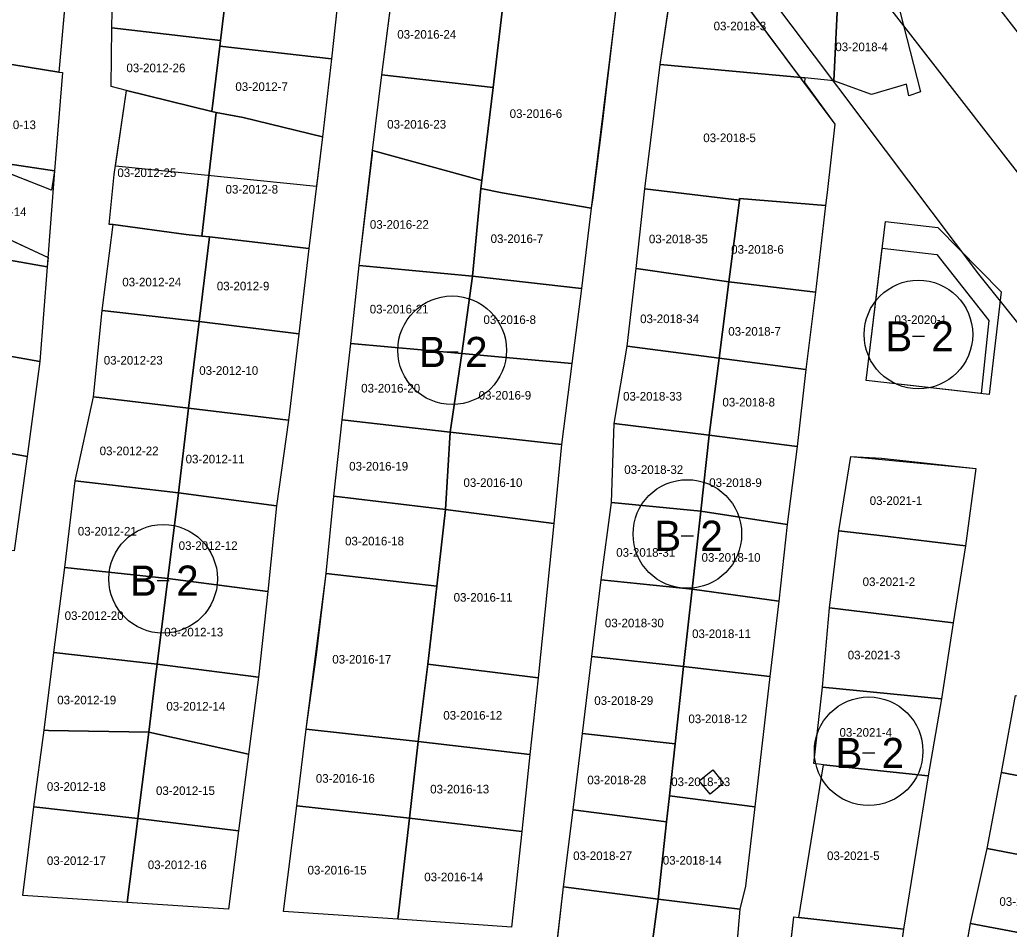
# Model space of a CAD drawing. Extents: x 413946 to 415528, y 4453939 to 4454944.
# Drawn here: x 414419.7 to 414534.5, y 4454655 to 4454760.5 of the extents above; entities that cross this region are included whole.
import ezdxf

# ---------------------------------------------------------------- set-up
doc = ezdxf.new("R2010")
doc.units = 0
for name, color, linetype in [('0_KADASTRO', 7, 'Continuous'), ('Level 27', 7, 'Continuous'), ('Level 29', 7, 'Continuous'), ('Level 54', 7, 'Continuous'), ('Level 62', 7, 'Continuous'), ('SEMBOL', 7, 'Continuous')]:
    doc.layers.add(name, color=color, linetype=linetype)

msp = doc.modelspace()

# ---------------------------------------------------------------- linework, layer by layer
at = {"layer": '0_KADASTRO'}
for points in [[(414411.09, 4454757.71), (414412.42, 4454768.39), (414424.89, 4454766.54), (414425.29, 4454766.49), (414424.24, 4454754.37), (414417.32, 4454755.48), (414417.48, 4454756.27), (414416.84, 4454756.42)], [(414430.38, 4454759.52), (414430.4, 4454761.44), (414431.26, 4454768.85), (414442.27, 4454767.59), (414443.18, 4454767.49), (414444.11, 4454767.4), (414442.98, 4454758.06)], [(414442.9, 4454757.4), (414442.98, 4454758.06), (414444.11, 4454767.4), (414456.96, 4454765.91), (414455.86, 4454755.93)], [(414461.7, 4454754.08), (414463.1, 4454764.94), (414475.92, 4454763.42), (414474.61, 4454752.59)], [(414494.02, 4454755.26), (414495.53, 4454765.54), (414514.68, 4454763.78), (414514.15, 4454753.38), (414510.8, 4454753.7)], [(414514.15, 4454753.38), (414514.68, 4454763.78), (414522.82, 4454763.48), (414523.07, 4454763.47), (414521.83, 4454761.44), (414524.23, 4454752.08), (414522.87, 4454751.64), (414522.59, 4454752.99), (414518.54, 4454751.77)], [(414473.21, 4454740.87), (414473.3, 4454741.81), (414474.61, 4454752.59), (414475.92, 4454763.42), (414488.85, 4454761.81), (414487.71, 4454752), (414487.32, 4454748.7), (414486.14, 4454739.52), (414486, 4454738.59), (414475.68, 4454740.39)], [(414430.3, 4454752.72), (414430.38, 4454759.52), (414442.98, 4454758.06), (414442.9, 4454757.4), (414441.97, 4454749.8), (414432.06, 4454752.24)], [(414441.97, 4454749.8), (414442.9, 4454757.4), (414455.86, 4454755.93), (414454.84, 4454746.86), (414445.62, 4454749.13), (414442.5, 4454749.69)], [(414414.39, 4454744.32), (414414.9, 4454747.24), (414416.84, 4454756.42), (414417.48, 4454756.27), (414417.32, 4454755.48), (414424.24, 4454754.37), (414424.66, 4454754.32), (414423.72, 4454742.92)], [(414492.24, 4454740.85), (414494.02, 4454755.26), (414510.8, 4454753.7), (414510.77, 4454753.18), (414514.29, 4454748.36), (414513.38, 4454740.43), (414513.21, 4454738.92), (414503.23, 4454739.74), (414503.2, 4454739.52)], [(414460.64, 4454745.28), (414461.7, 4454754.08), (414474.61, 4454752.59), (414473.3, 4454741.81)], [(414430.05, 4454736.72), (414430.65, 4454742.52), (414432.06, 4454752.24), (414441.97, 4454749.8), (414442.5, 4454749.69), (414440.81, 4454735.35), (414439.01, 4454735.53), (414430.52, 4454736.69)], [(414440.81, 4454735.35), (414442.5, 4454749.69), (414445.62, 4454749.13), (414454.84, 4454746.86), (414453.25, 4454733.91), (414441.72, 4454735.26)], [(414412.99, 4454733.55), (414413.48, 4454737.28), (414414.39, 4454744.32), (414423.72, 4454742.92), (414422.89, 4454731.8)], [(414459.08, 4454731.97), (414459.3, 4454733.89), (414460.63, 4454744.86), (414460.64, 4454745.28), (414473.3, 4454741.81), (414473.21, 4454740.87), (414472.22, 4454730.73)], [(414472.22, 4454730.73), (414473.21, 4454740.87), (414475.68, 4454740.39), (414486, 4454738.59), (414484.86, 4454729.29)], [(414491.24, 4454731.59), (414492.24, 4454740.85), (414503.2, 4454739.52), (414501.98, 4454730.07)], [(414501.98, 4454730.07), (414503.2, 4454739.52), (414503.23, 4454739.74), (414513.21, 4454738.92), (414512.05, 4454728.87)], [(414429.27, 4454726.72), (414430.52, 4454736.69), (414439.01, 4454735.53), (414440.81, 4454735.35), (414441.72, 4454735.26), (414440.51, 4454725.47)], [(414517.93, 4454718.61), (414520.15, 4454737.04), (414526.21, 4454736.36), (414533.56, 4454728.9), (414532.17, 4454717)], [(414440.51, 4454725.47), (414441.72, 4454735.26), (414453.25, 4454733.91), (414452.09, 4454724.02)], [(414411.31, 4454722.72), (414412.02, 4454727.29), (414412.99, 4454733.55), (414422.89, 4454731.8), (414422.02, 4454720.81)], [(414458.1, 4454722.9), (414459.08, 4454731.97), (414472.22, 4454730.73), (414470.99, 4454721.74)], [(414490.16, 4454722.6), (414491.24, 4454731.59), (414501.98, 4454730.07), (414500.84, 4454721.21)], [(414470.99, 4454721.74), (414472.22, 4454730.73), (414484.86, 4454729.29), (414483.76, 4454720.58)], [(414500.84, 4454721.21), (414501.98, 4454730.07), (414512.05, 4454728.87), (414510.91, 4454719.88)], [(414428.26, 4454716.73), (414429.27, 4454726.72), (414440.51, 4454725.47), (414439.26, 4454715.41)], [(414439.26, 4454715.41), (414440.51, 4454725.47), (414452.09, 4454724.02), (414450.88, 4454714.03)], [(414409.93, 4454711.73), (414410.66, 4454717.54), (414411.31, 4454722.72), (414422.02, 4454720.81), (414420.54, 4454709.81)], [(414457.12, 4454714.06), (414458.1, 4454722.9), (414470.99, 4454721.74), (414469.65, 4454712.64)], [(414488.68, 4454713.62), (414490.16, 4454722.6), (414500.84, 4454721.21), (414499.69, 4454712.26)], [(414469.65, 4454712.64), (414470.99, 4454721.74), (414483.76, 4454720.58), (414482.56, 4454711.21)], [(414499.69, 4454712.26), (414500.84, 4454721.21), (414510.91, 4454719.88), (414509.89, 4454710.97)], [(414426.12, 4454706.97), (414428.26, 4454716.73), (414439.26, 4454715.41), (414438.13, 4454705.58)], [(414438.13, 4454705.58), (414439.26, 4454715.41), (414450.88, 4454714.03), (414449.5, 4454704.08)], [(414456.15, 4454705.18), (414457.12, 4454714.06), (414469.65, 4454712.64), (414469.08, 4454703.67)], [(414488.34, 4454704.47), (414488.68, 4454713.62), (414499.69, 4454712.26), (414498.71, 4454703.47)], [(414469.08, 4454703.67), (414469.65, 4454712.64), (414482.56, 4454711.21), (414481.66, 4454702.04)], [(414498.71, 4454703.47), (414499.69, 4454712.26), (414509.89, 4454710.97), (414508.74, 4454701.9)], [(414408.52, 4454700.53), (414409.4, 4454707.53), (414409.93, 4454711.73), (414420.54, 4454709.81), (414419.04, 4454698.87), (414418.26, 4454698.94)], [(414514.73, 4454701.17), (414516.13, 4454709.81), (414519.69, 4454709.59), (414530.63, 4454708.39), (414529.43, 4454699.42), (414519.81, 4454700.58)], [(414424.91, 4454696.94), (414426.12, 4454706.97), (414438.13, 4454705.58), (414436.88, 4454695.64)], [(414436.88, 4454695.64), (414438.13, 4454705.58), (414449.5, 4454704.08), (414448.47, 4454694.14)], [(414455.26, 4454696.22), (414456.15, 4454705.18), (414469.08, 4454703.67), (414468.08, 4454694.75)], [(414487.17, 4454695.5), (414488.34, 4454704.47), (414498.71, 4454703.47), (414497.71, 4454694.41)], [(414467.06, 4454685.72), (414468.08, 4454694.75), (414469.08, 4454703.67), (414481.66, 4454702.04), (414479.83, 4454684.13)], [(414497.71, 4454694.41), (414498.71, 4454703.47), (414508.74, 4454701.9), (414507.78, 4454693.01)], [(414513.64, 4454692.23), (414514.73, 4454701.17), (414519.81, 4454700.58), (414529.43, 4454699.42), (414528, 4454690.52)], [(414423.66, 4454687.08), (414424.91, 4454696.94), (414436.88, 4454695.64), (414435.64, 4454685.73)], [(414452.93, 4454678.19), (414454.13, 4454686.78), (414455.26, 4454696.22), (414468.08, 4454694.75), (414467.06, 4454685.72), (414465.93, 4454676.76)], [(414435.64, 4454685.73), (414436.88, 4454695.64), (414448.47, 4454694.14), (414447.39, 4454684.22)], [(414486.08, 4454686.59), (414487.17, 4454695.5), (414497.71, 4454694.41), (414496.71, 4454685.45)], [(414496.71, 4454685.45), (414497.71, 4454694.41), (414507.78, 4454693.01), (414506.74, 4454684.3)], [(414512.84, 4454683.03), (414513.64, 4454692.23), (414528, 4454690.52), (414526.67, 4454681.7)], [(414422.53, 4454678.05), (414423.66, 4454687.08), (414435.64, 4454685.73), (414435.45, 4454684.28), (414434.65, 4454677.83), (414423.03, 4454678.01)], [(414434.65, 4454677.83), (414435.45, 4454684.28), (414435.64, 4454685.73), (414447.39, 4454684.22), (414446.22, 4454675.29)], [(414465.93, 4454676.76), (414467.06, 4454685.72), (414479.83, 4454684.13), (414478.87, 4454675.25)], [(414484.99, 4454677.67), (414486.08, 4454686.59), (414496.71, 4454685.45), (414495.73, 4454676.48)], [(414495.07, 4454670.43), (414495.73, 4454676.48), (414496.71, 4454685.45), (414506.74, 4454684.3), (414505, 4454669.16)], [(414511.83, 4454674.18), (414512.84, 4454683.03), (414526.67, 4454681.7), (414525.12, 4454672.75), (414512.97, 4454674.05)], [(414533.61, 4454673.15), (414535.24, 4454682.06), (414550.8, 4454679.07), (414549.12, 4454670.2)], [(414421.32, 4454669.17), (414422.53, 4454678.05), (414423.03, 4454678.01), (414434.65, 4454677.83), (414433.39, 4454667.83)], [(414433.39, 4454667.83), (414434.65, 4454677.83), (414446.22, 4454675.29), (414445.07, 4454666.4)], [(414451.84, 4454669.3), (414452.93, 4454678.19), (414465.93, 4454676.76), (414464.93, 4454667.87)], [(414483.9, 4454668.83), (414484.99, 4454677.67), (414495.73, 4454676.48), (414495.07, 4454670.43), (414494.74, 4454667.42)], [(414464.93, 4454667.87), (414465.93, 4454676.76), (414478.87, 4454675.25), (414477.96, 4454666.3)], [(414498.54, 4454672.2), (414500.1, 4454673.47), (414501.34, 4454671.9), (414499.79, 4454670.63)], [(414498.54, 4454672.2), (414500.1, 4454673.47), (414501.34, 4454671.9), (414499.79, 4454670.63)], [(414510.1, 4454656.34), (414512.97, 4454674.05), (414525.12, 4454672.75), (414522.25, 4454654.98)], [(414531.97, 4454664.33), (414533.61, 4454673.15), (414549.12, 4454670.2), (414547.45, 4454661.37)], [(414493.77, 4454658.47), (414494.74, 4454667.42), (414495.07, 4454670.43), (414505, 4454669.16), (414503.89, 4454659.98), (414503.24, 4454657.28)], [(414420.05, 4454658.87), (414421.32, 4454669.17), (414433.39, 4454667.83), (414432.16, 4454658.08)], [(414450.31, 4454657.04), (414451.84, 4454669.3), (414464.93, 4454667.87), (414463.58, 4454656.13)], [(414482.8, 4454659.87), (414483.9, 4454668.83), (414494.74, 4454667.42), (414493.77, 4454658.47)], [(414432.16, 4454658.08), (414433.39, 4454667.83), (414445.07, 4454666.4), (414443.91, 4454657.28)], [(414463.58, 4454656.13), (414464.93, 4454667.87), (414477.96, 4454666.3), (414476.77, 4454655.19)], [(414530.01, 4454655.62), (414531.97, 4454664.33), (414547.45, 4454661.37), (414545.83, 4454652.65)], [(414481.74, 4454650.84), (414482.8, 4454659.87), (414493.77, 4454658.47), (414492.58, 4454649.49)], [(414492.58, 4454649.49), (414493.77, 4454658.47), (414503.24, 4454657.28), (414502.46, 4454648.25)], [(414508.5, 4454647.45), (414509.5, 4454656.41), (414510.1, 4454656.34), (414522.25, 4454654.98), (414520.98, 4454645.92)], [(414528.46, 4454646.74), (414530.01, 4454655.62), (414545.83, 4454652.65), (414544.19, 4454643.58)]]:
    msp.add_lwpolyline(points, close=True, dxfattribs=at)
at = {"layer": 'Level 27'}
for p, q in [((414425.29, 4454766.49), (414424.24, 4454754.37)), ((414456.96, 4454765.91), (414455.86, 4454755.93)), ((414461.7, 4454754.08), (414463.1, 4454764.94)), ((414494.02, 4454755.26), (414495.42, 4454764.81)), ((414430.38, 4454759.52), (414430.4, 4454761.44)), ((414488.85, 4454761.81), (414486, 4454738.59)), ((414430.3, 4454752.72), (414430.38, 4454759.52)), ((414455.86, 4454755.93), (414454.84, 4454746.86)), ((414492.24, 4454740.85), (414494.02, 4454755.26)), ((414424.66, 4454754.32), (414423.72, 4454742.92)), ((414424.24, 4454754.37), (414424.66, 4454754.32)), ((414460.64, 4454745.28), (414461.7, 4454754.08)), ((414432.06, 4454752.24), (414430.3, 4454752.72)), ((414430.79, 4454743.48), (414432.06, 4454752.24)), ((414423.36, 4454740.7), (414404.07, 4454748.25)), ((414454.84, 4454746.86), (414454.13, 4454741.1)), ((414459.08, 4454731.97), (414460.64, 4454745.28)), ((414454.13, 4454741.1), (414430.79, 4454743.48)), ((414423.72, 4454742.92), (414423.36, 4454740.7)), ((414491.24, 4454731.59), (414492.24, 4454740.85)), ((414486, 4454738.59), (414484.86, 4454729.29)), ((414513.21, 4454738.92), (414512.05, 4454728.87)), ((414413.48, 4454737.28), (414422.97, 4454732.88)), ((414429.27, 4454726.72), (414430.52, 4454736.69)), ((414430.52, 4454736.69), (414439.01, 4454735.53)), ((414439.01, 4454735.53), (414440.81, 4454735.35)), ((414440.81, 4454735.35), (414441.72, 4454735.26)), ((414441.72, 4454735.26), (414453.25, 4454733.91)), ((414453.25, 4454733.91), (414452.09, 4454724.02)), ((414517.93, 4454718.61), (414519.78, 4454733.95)), ((414422.97, 4454732.88), (414422.89, 4454731.8)), ((414422.89, 4454731.8), (414422.02, 4454720.81)), ((414458.1, 4454722.9), (414459.08, 4454731.97)), ((414490.16, 4454722.6), (414491.24, 4454731.59)), ((414484.86, 4454729.29), (414483.76, 4454720.58)), ((414512.05, 4454728.87), (414510.91, 4454719.88)), ((414428.26, 4454716.73), (414429.27, 4454726.72)), ((414452.09, 4454724.02), (414450.88, 4454714.03)), ((414457.12, 4454714.06), (414458.1, 4454722.9)), ((414488.68, 4454713.62), (414490.16, 4454722.6)), ((414422.02, 4454720.81), (414420.54, 4454709.81)), ((414483.76, 4454720.58), (414482.56, 4454711.21)), ((414510.91, 4454719.88), (414509.89, 4454710.97)), ((414531.26, 4454717.1), (414517.93, 4454718.61)), ((414426.12, 4454706.97), (414428.26, 4454716.73)), ((414450.88, 4454714.03), (414449.5, 4454704.08)), ((414456.15, 4454705.18), (414457.12, 4454714.06)), ((414488.34, 4454704.47), (414488.68, 4454713.62)), ((414482.56, 4454711.21), (414481.66, 4454702.04)), ((414509.89, 4454710.97), (414508.74, 4454701.9)), ((414420.54, 4454709.81), (414419.04, 4454698.87)), ((414514.73, 4454701.17), (414516.13, 4454709.81)), ((414516.13, 4454709.81), (414530.63, 4454708.39)), ((414530.63, 4454708.39), (414529.43, 4454699.42)), ((414424.91, 4454696.94), (414426.12, 4454706.97)), ((414455.26, 4454696.22), (414456.15, 4454705.18)), ((414449.5, 4454704.08), (414448.47, 4454694.14)), ((414487.17, 4454695.5), (414488.34, 4454704.47)), ((414481.66, 4454702.04), (414479.83, 4454684.13)), ((414508.74, 4454701.9), (414507.78, 4454693.01)), ((414513.64, 4454692.23), (414514.73, 4454701.17)), ((414529.43, 4454699.42), (414528, 4454690.52)), ((414423.66, 4454687.08), (414424.91, 4454696.94)), ((414452.93, 4454678.19), (414455.26, 4454696.22)), ((414486.08, 4454686.59), (414487.17, 4454695.5)), ((414448.47, 4454694.14), (414447.39, 4454684.22)), ((414507.78, 4454693.01), (414506.74, 4454684.3)), ((414512.84, 4454683.03), (414513.64, 4454692.23)), ((414528, 4454690.52), (414526.67, 4454681.7)), ((414422.53, 4454678.05), (414423.66, 4454687.08)), ((414484.99, 4454677.67), (414486.08, 4454686.59)), ((414447.39, 4454684.22), (414446.22, 4454675.29)), ((414479.83, 4454684.13), (414478.87, 4454675.25)), ((414506.74, 4454684.3), (414505, 4454669.16)), ((414511.83, 4454674.18), (414512.84, 4454683.03)), ((414526.67, 4454681.7), (414525.12, 4454672.75)), ((414533.61, 4454673.15), (414535.24, 4454682.06)), ((414421.32, 4454669.17), (414422.53, 4454678.05)), ((414451.84, 4454669.3), (414452.93, 4454678.19)), ((414483.9, 4454668.83), (414484.99, 4454677.67)), ((414446.22, 4454675.29), (414445.07, 4454666.4)), ((414478.87, 4454675.25), (414477.96, 4454666.3)), ((414512.97, 4454674.05), (414511.83, 4454674.18)), ((414510.1, 4454656.34), (414512.97, 4454674.05)), ((414531.97, 4454664.33), (414533.61, 4454673.15)), ((414525.12, 4454672.75), (414522.25, 4454654.98)), ((414420.05, 4454658.87), (414421.32, 4454669.17)), ((414450.31, 4454657.04), (414451.84, 4454669.3)), ((414482.8, 4454659.87), (414483.9, 4454668.83)), ((414505, 4454669.16), (414503.89, 4454659.98)), ((414445.07, 4454666.4), (414443.91, 4454657.28)), ((414477.96, 4454666.3), (414476.77, 4454655.19)), ((414530.01, 4454655.62), (414531.97, 4454664.33)), ((414481.74, 4454650.84), (414482.8, 4454659.87)), ((414503.89, 4454659.98), (414503.24, 4454657.28)), ((414432.16, 4454658.08), (414420.05, 4454658.87)), ((414443.91, 4454657.28), (414432.16, 4454658.08)), ((414463.58, 4454656.13), (414450.31, 4454657.04)), ((414503.24, 4454657.28), (414502.46, 4454648.25)), ((414476.77, 4454655.19), (414463.58, 4454656.13)), ((414508.5, 4454647.45), (414509.5, 4454656.41)), ((414509.5, 4454656.41), (414510.1, 4454656.34)), ((414522.25, 4454654.98), (414520.98, 4454645.92)), ((414528.46, 4454646.74), (414530.01, 4454655.62))]:
    msp.add_line(p, q, dxfattribs=at)
at = {"layer": 'Level 29'}
for p, q in [((414502.57, 4454764.08), (414514.29, 4454748.36)), ((414514.29, 4454748.36), (414513.38, 4454740.43)), ((414513.38, 4454740.43), (414513.21, 4454738.92)), ((414519.78, 4454733.95), (414526.1, 4454733.21)), ((414526.1, 4454733.21), (414532.15, 4454725.56)), ((414532.15, 4454725.56), (414531.26, 4454717.1))]:
    msp.add_line(p, q, dxfattribs=at)
at = {"layer": 'Level 54'}
for points in [[(414431.26, 4454768.85), (414432.2, 4454777.98), (414433.33, 4454786.77), (414434.42, 4454795.71), (414435.4, 4454804.76), (414448.3, 4454802.97), (414450.51, 4454802.83), (414461.23, 4454801.5), (414460.29, 4454792.57), (414459.59, 4454792.67), (414458.52, 4454783.8), (414459.16, 4454783.71), (414458.02, 4454774.76), (414456.96, 4454765.91), (414455.86, 4454755.93), (414454.84, 4454746.86), (414454.13, 4454741.1), (414430.79, 4454743.48), (414432.06, 4454752.24), (414430.3, 4454752.72), (414430.38, 4454759.52), (414430.4, 4454761.44)], [(414426.12, 4454706.97), (414428.26, 4454716.73), (414429.27, 4454726.72), (414430.52, 4454736.69), (414439.01, 4454735.53), (414440.81, 4454735.35), (414441.72, 4454735.26), (414453.25, 4454733.91), (414452.09, 4454724.02), (414450.88, 4454714.03), (414449.5, 4454704.08), (414448.47, 4454694.14), (414447.39, 4454684.22), (414446.22, 4454675.29), (414445.07, 4454666.4), (414443.91, 4454657.28), (414432.16, 4454658.08), (414420.05, 4454658.87), (414421.32, 4454669.17), (414422.53, 4454678.05), (414423.66, 4454687.08), (414424.91, 4454696.94)], [(414531.26, 4454717.1), (414517.93, 4454718.61), (414519.78, 4454733.95), (414526.1, 4454733.21), (414532.15, 4454725.56)], [(414529.43, 4454699.42), (414528, 4454690.52), (414526.67, 4454681.7), (414525.12, 4454672.75), (414522.25, 4454654.98), (414520.98, 4454645.92), (414520.61, 4454638.91), (414507.58, 4454639.13), (414508.5, 4454647.45), (414509.5, 4454656.41), (414510.1, 4454656.34), (414512.97, 4454674.05), (414511.83, 4454674.18), (414512.84, 4454683.03), (414513.64, 4454692.23), (414514.73, 4454701.17), (414516.13, 4454709.81), (414530.63, 4454708.39)]]:
    msp.add_lwpolyline(points, close=True, dxfattribs=at)
for points in [[(414425.29, 4454766.49), (414424.24, 4454754.37), (414424.66, 4454754.32), (414423.72, 4454742.92), (414423.36, 4454740.7), (414404.07, 4454748.25), (414404.12, 4454748.71), (414405.91, 4454758.87), (414404.37, 4454759.19), (414403.75, 4454780.34)], [(414488.85, 4454761.81), (414486, 4454738.59), (414484.86, 4454729.29), (414483.76, 4454720.58), (414482.56, 4454711.21), (414481.66, 4454702.04), (414479.83, 4454684.13), (414478.87, 4454675.25), (414477.96, 4454666.3), (414476.77, 4454655.19), (414463.58, 4454656.13), (414450.31, 4454657.04), (414451.84, 4454669.3), (414452.93, 4454678.19), (414455.26, 4454696.22), (414456.15, 4454705.18), (414457.12, 4454714.06), (414458.1, 4454722.9), (414459.08, 4454731.97), (414460.64, 4454745.28), (414461.7, 4454754.08), (414463.1, 4454764.94)], [(414481.74, 4454650.84), (414482.8, 4454659.87), (414483.9, 4454668.83), (414484.99, 4454677.67), (414486.08, 4454686.59), (414487.17, 4454695.5), (414488.34, 4454704.47), (414488.68, 4454713.62), (414490.16, 4454722.6), (414491.24, 4454731.59), (414492.24, 4454740.85), (414494.02, 4454755.26), (414495.42, 4454764.81)], [(414502.57, 4454764.08), (414514.29, 4454748.36), (414513.38, 4454740.43), (414513.21, 4454738.92), (414512.05, 4454728.87), (414510.91, 4454719.88), (414509.89, 4454710.97), (414508.74, 4454701.9), (414507.78, 4454693.01), (414506.74, 4454684.3), (414505, 4454669.16), (414503.89, 4454659.98), (414503.24, 4454657.28), (414502.46, 4454648.25)], [(414413.48, 4454737.28), (414422.97, 4454732.88), (414422.89, 4454731.8), (414422.02, 4454720.81), (414420.54, 4454709.81), (414419.04, 4454698.87)], [(414542.08, 4454560.27), (414532.23, 4454562.05), (414530.21, 4454562.48), (414523.33, 4454563.86), (414524.03, 4454574.48), (414524.73, 4454585.08), (414525.45, 4454594.07), (414526.27, 4454603.07), (414526.64, 4454611.98), (414527.31, 4454622.28), (414527.62, 4454628.59), (414528.55, 4454636.92), (414526.72, 4454637.26), (414528.46, 4454646.74), (414530.01, 4454655.62), (414531.97, 4454664.33), (414533.61, 4454673.15), (414535.24, 4454682.06)]]:
    msp.add_lwpolyline(points, dxfattribs=at)
at = {"layer": 'Level 62'}
msp.add_line((414490.2, 4454817.75), (414671.82, 4454581.99), dxfattribs=at)
for points in [[(414436.69, 4454870.01), (414438.28, 4454867.85), (414632.33, 4454618.11)], [(414437.61, 4454853.57), (414465.73, 4454817.59), (414530.96, 4454730.93), (414621.16, 4454618.45)]]:
    msp.add_lwpolyline(points, dxfattribs=at)
at = {"layer": 'SEMBOL'}
for p, q in [((414523.27, 4454723.74), (414524.67, 4454723.74)), ((414469.17, 4454721.92), (414470.57, 4454721.92)), ((414496.46, 4454700.6), (414497.86, 4454700.6)), ((414435.63, 4454695.4), (414437.03, 4454695.4)), ((414517.5, 4454675.41), (414518.9, 4454675.41))]:
    msp.add_line(p, q, dxfattribs=at)
for centre in [(414523.97, 4454723.95), (414469.87, 4454722.12), (414497.16, 4454700.81), (414436.33, 4454695.61), (414518.2, 4454675.61)]:
    msp.add_circle(centre, 6.3, dxfattribs=at)

# ---------------------------------------------------------------- texts
at = {"layer": '0_KADASTRO'}
for s, p in [('03-2016-24', (414463.5, 4454758.26)), ('03-2018-3', (414500.21, 4454759.23)), ('03-2018-4', (414514.33, 4454756.81)), ('03-2012-26', (414432.07, 4454754.37)), ('03-2012-7', (414444.71, 4454752.2)), ('03-2016-6', (414476.54, 4454749.07)), ('03-2016-23', (414462.33, 4454747.83)), ('03-2010-13', (414414.73, 4454747.77)), ('03-2018-5', (414499.01, 4454746.26)), ('03-2012-25', (414431.02, 4454742.21)), ('03-2012-8', (414443.57, 4454740.29)), ('03-2010-14', (414413.63, 4454737.68)), ('03-2016-22', (414460.32, 4454736.21)), ('03-2016-7', (414474.33, 4454734.56)), ('03-2018-35', (414492.7, 4454734.53)), ('03-2018-6', (414502.25, 4454733.32)), ('03-2012-24', (414431.59, 4454729.53)), ('03-2012-9', (414442.56, 4454729.07)), ('03-2016-21', (414460.3, 4454726.39)), ('03-2016-8', (414473.5, 4454725.17)), ('03-2018-34', (414491.68, 4454725.27)), ('03-2020-1', (414521.19, 4454725.17)), ('03-2018-7', (414501.91, 4454723.81)), ('03-2012-23', (414429.44, 4454720.46)), ('03-2012-10', (414440.52, 4454719.27)), ('03-2016-20', (414459.31, 4454717.22)), ('03-2016-9', (414472.94, 4454716.4)), ('03-2018-33', (414489.7, 4454716.28)), ('03-2018-8', (414501.23, 4454715.6)), ('03-2012-22', (414428.96, 4454709.95)), ('03-2012-11', (414438.94, 4454709)), ('03-2016-19', (414457.92, 4454708.17)), ('03-2018-32', (414489.84, 4454707.78)), ('03-2016-10', (414471.18, 4454706.27)), ('03-2018-9', (414499.7, 4454706.27)), ('03-2021-1', (414518.32, 4454704.18)), ('03-2012-21', (414426.43, 4454700.63)), ('03-2012-12', (414438.13, 4454698.96)), ('03-2016-18', (414457.44, 4454699.49)), ('03-2018-31', (414488.91, 4454698.17)), ('03-2018-10', (414498.81, 4454697.59)), ('03-2021-2', (414517.5, 4454694.77)), ('03-2016-11', (414470.04, 4454692.96)), ('03-2012-20', (414424.9, 4454690.84)), ('03-2018-30', (414487.59, 4454689.99)), ('03-2012-13', (414436.46, 4454688.93)), ('03-2018-11', (414497.71, 4454688.74)), ('03-2021-3', (414515.77, 4454686.27)), ('03-2016-17', (414455.96, 4454685.78)), ('03-2012-19', (414424.04, 4454681.05)), ('03-2012-14', (414436.7, 4454680.33)), ('03-2018-29', (414486.36, 4454680.99)), ('03-2016-12', (414468.84, 4454679.28)), ('03-2018-12', (414497.28, 4454678.87)), ('03-2021-4', (414514.82, 4454677.3)), ('03-2012-18', (414422.84, 4454671.02)), ('03-2016-16', (414454.05, 4454671.96)), ('03-2018-28', (414485.55, 4454671.78)), ('03-2018-13', (414495.29, 4454671.57)), ('03-2012-15', (414435.5, 4454670.54)), ('03-2016-13', (414467.32, 4454670.72)), ('03-2018-27', (414483.91, 4454662.99)), ('03-2021-5', (414513.37, 4454662.99)), ('03-2012-17', (414422.84, 4454662.42)), ('03-2012-16', (414434.55, 4454661.94)), ('03-2018-14', (414494.31, 4454662.46)), ('03-2016-15', (414453.09, 4454661.32)), ('03-2016-14', (414466.63, 4454660.53)), ('03-2023-24', (414533.37, 4454657.68))]:
    msp.add_text(s, height=1, dxfattribs=at).set_placement(p)
at = {"layer": 'SEMBOL'}
for s, p in [('B', (414520.13, 4454721.99)), ('2', (414525.48, 4454721.99)), ('B', (414466.02, 4454720.17)), ('2', (414471.37, 4454720.17)), ('B', (414493.32, 4454698.85)), ('2', (414498.67, 4454698.85)), ('B', (414432.48, 4454693.65)), ('2', (414437.84, 4454693.65)), ('B', (414514.35, 4454673.66)), ('2', (414519.71, 4454673.66))]:
    msp.add_text(s, height=3.5, dxfattribs=at).set_placement(p)

doc.saveas('drawing.dxf')
